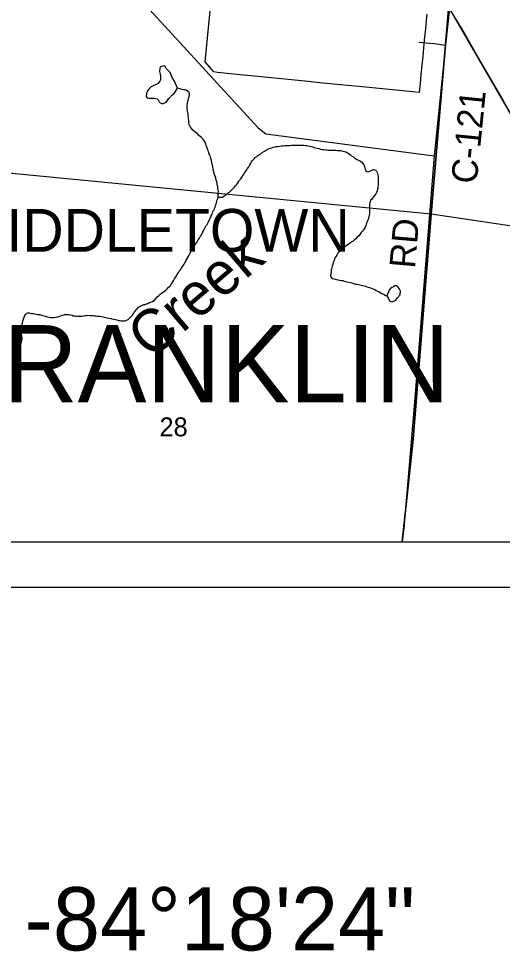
# Model space of a CAD drawing. Extents: x -7.3 to 34, y 0 to 22.
# Drawn here: x 6.481 to 7.551, y 13.194 to 15.258 of the extents above; entities that cross this region are included whole.
import ezdxf

# ---------------------------------------------------------------- set-up
doc = ezdxf.new("R2010")
doc.units = 0
for name, color, linetype in [('GM_X_Corporation', 7, 'Continuous'), ('GM_X_Corporation_Text', 7, 'Continuous'), ('GM_X_County_Road', 7, 'Continuous'), ('GM_X_County_Road_Text', 7, 'Continuous'), ('GM_X_Minor_River', 7, 'Continuous'), ('GM_X_Minor_River_Text', 7, 'Continuous'), ('GM_X_Rail_Line', 7, 'Continuous'), ('GM_X_Section_Text', 7, 'Continuous'), ('GM_X_State_Route', 7, 'Continuous'), ('GM_X_Township_Road', 7, 'Continuous'), ('GM_X_Township_Text', 7, 'Continuous'), ('SH_Data', 7, 'Continuous'), ('SH_Text', 7, 'Continuous')]:
    doc.layers.add(name, color=color, linetype=linetype)

msp = doc.modelspace()

# ---------------------------------------------------------------- linework, layer by layer
at = {"layer": 'GM_X_Corporation'}
for points in [[(4.3152, 15.5847), (4.2701, 15.1232), (4.2655, 15.0758), (4.2591, 15.0066), (4.246, 14.8644), (4.233, 14.7229), (4.2199, 14.5807), (4.1921, 14.279), (4.1756, 14.1), (8.9, 14.1), (8.9, 19.7858)], [(4.3152, 15.5847), (4.2701, 15.1232), (4.2655, 15.0758), (4.2591, 15.0066), (4.246, 14.8644), (4.233, 14.7229), (4.2199, 14.5807), (4.1921, 14.279), (4.1756, 14.1), (8.3447, 14.1), (8.3604, 14.2653), (8.3676, 14.3403), (8.3685, 14.3492), (8.4214, 14.9056), (8.4562, 15.2161), (8.4601, 15.2687)], [(7.3841, 15.2677), (7.3828, 15.254), (7.381, 15.2352), (7.3786, 15.2107), (7.3776, 15.2013), (7.375, 15.1745), (7.3731, 15.1544), (7.3711, 15.1342), (7.3691, 15.1141), (7.3671, 15.0939), (7.2494, 15.1056), (7.1858, 15.112), (7.1538, 15.1151), (7.1217, 15.1182), (6.9882, 15.1318), (6.9781, 15.1328), (6.9209, 15.1386), (6.9127, 15.1395), (6.8935, 15.1619), (6.8943, 15.1697), (6.9158, 15.3877)]]:
    msp.add_lwpolyline(points, dxfattribs=at)
for points in [[(6.4371, 15.9508), (7.4799, 15.8457), (7.3939, 14.8252), (6.3438, 14.9266)], [(7.4799, 15.8457), (8.4992, 15.7029), (8.4066, 14.6743), (7.3939, 14.8252)], [(6.2678, 14.1), (7.3299, 14.1), (7.354, 14.3269), (7.3939, 14.8252), (6.3438, 14.9266)], [(7.3299, 14.1), (8.355, 14.1), (8.4066, 14.6743), (7.3939, 14.8252), (7.354, 14.3269)]]:
    msp.add_lwpolyline(points, close=True, dxfattribs=at)
at = {"layer": 'GM_X_County_Road'}
for points in [[(5.9101, 15.654), (6.405, 15.6216), (6.39, 15.4485), (6.3969, 15.4388), (6.6396, 15.4146), (6.6541, 15.4047), (7.0106, 15.016), (7.0281, 15.003), (7.4002, 14.9537)], [(7.4344, 15.2802), (7.4256, 15.1989), (7.4002, 14.9537), (7.3569, 14.4092), (7.3329, 14.1292), (7.3296, 14.1)]]:
    msp.add_lwpolyline(points, dxfattribs=at)
at = {"layer": 'GM_X_Minor_River'}
for points in [[(6.8323, 15.1035), (6.8257, 15.1194), (6.8203, 15.1276), (6.8161, 15.1387), (6.8073, 15.1474), (6.8045, 15.1528), (6.7995, 15.1526), (6.7949, 15.1512), (6.7929, 15.1478), (6.7927, 15.1403), (6.7936, 15.1349), (6.7949, 15.1292), (6.7943, 15.122), (6.7931, 15.1193), (6.7891, 15.1138), (6.7837, 15.1113), (6.7783, 15.1088), (6.7741, 15.1067), (6.7697, 15.1022), (6.7662, 15.0978), (6.7633, 15.0918), (6.7631, 15.0854), (6.7653, 15.0823), (6.769, 15.0814), (6.7763, 15.0819), (6.7808, 15.0814), (6.7842, 15.0809), (6.7876, 15.0804), (6.7898, 15.078), (6.7916, 15.0738), (6.7941, 15.0714), (6.796, 15.0706), (6.7994, 15.0694)], [(6.7994, 15.0694), (6.8075, 15.0725), (6.8134, 15.0807), (6.8197, 15.0881), (6.8256, 15.0925), (6.8323, 15.1035)], [(6.9226, 14.8722), (6.9227, 14.8748), (6.9223, 14.8779), (6.9217, 14.8821), (6.9214, 14.8863), (6.9203, 14.8901), (6.92, 14.8931), (6.919, 14.8966), (6.9179, 14.9004), (6.9169, 14.905), (6.9154, 14.9088), (6.9144, 14.913), (6.913, 14.9176), (6.9123, 14.9218), (6.9112, 14.9252), (6.9102, 14.9298), (6.9095, 14.9333), (6.9092, 14.9359), (6.9085, 14.939), (6.9075, 14.9436), (6.906, 14.9478), (6.905, 14.9516), (6.9039, 14.9547), (6.9025, 14.9585), (6.9011, 14.9631), (6.9, 14.9658), (6.8989, 14.9684), (6.8971, 14.973), (6.896, 14.9769), (6.8953, 14.9795), (6.8932, 14.9841), (6.8906, 14.9884), (6.8888, 14.9911), (6.8854, 14.9942), (6.8824, 14.9965), (6.8798, 14.9992), (6.8772, 15.0016), (6.8732, 15.0055), (6.8698, 15.0078), (6.8664, 15.0106), (6.8639, 15.014), (6.8613, 15.0171), (6.8594, 15.0202), (6.8584, 15.0236), (6.8577, 15.0263), (6.8574, 15.0294), (6.8571, 15.0328), (6.8567, 15.0355), (6.8564, 15.0389), (6.8561, 15.0431), (6.8558, 15.0461), (6.8552, 15.0495), (6.8545, 15.0526), (6.8538, 15.0587), (6.8536, 15.0636), (6.8536, 15.0663), (6.8541, 15.0689), (6.8541, 15.0716), (6.8549, 15.0746), (6.8558, 15.0773), (6.8566, 15.0799), (6.8574, 15.0829), (6.8582, 15.0856), (6.8587, 15.089), (6.8591, 15.0916), (6.858, 15.0951), (6.8547, 15.0974), (6.8513, 15.099), (6.8487, 15.0998), (6.8453, 15.1003), (6.8419, 15.1011), (6.8385, 15.102), (6.8351, 15.1028), (6.8323, 15.1035)], [(6.9224, 14.8623), (6.9315, 14.8625), (6.9353, 14.8655), (6.938, 14.8669), (6.9419, 14.8702), (6.9454, 14.8725), (6.9481, 14.8747), (6.9515, 14.878), (6.955, 14.881), (6.9585, 14.8847), (6.9609, 14.8873), (6.9628, 14.8899), (6.9651, 14.8929), (6.9675, 14.8963), (6.9687, 14.8993), (6.9726, 14.9034), (6.9753, 14.9075), (6.9769, 14.9105), (6.98, 14.9139), (6.9816, 14.9169), (6.984, 14.9206), (6.9855, 14.9232), (6.9871, 14.9259), (6.9898, 14.93), (6.9922, 14.9341), (6.9946, 14.9379), (6.9962, 14.9409), (6.9985, 14.9439), (7.0016, 14.9472), (7.0043, 14.9506), (7.007, 14.952), (7.0101, 14.9546), (7.014, 14.9568), (7.0166, 14.9587), (7.0197, 14.9613), (7.0247, 14.9646), (7.0293, 14.9671), (7.0339, 14.9693), (7.0374, 14.9708), (7.0412, 14.9718), (7.045, 14.9729), (7.0481, 14.9736), (7.0507, 14.9743), (7.0546, 14.9749), (7.0587, 14.9756), (7.0622, 14.9759), (7.066, 14.9762), (7.0698, 14.9765), (7.0736, 14.9768), (7.077, 14.9771), (7.0808, 14.977), (7.0849, 14.9773), (7.0891, 14.9776), (7.0918, 14.9775), (7.0967, 14.9778), (7.1009, 14.9777), (7.1043, 14.9777), (7.1073, 14.9776), (7.1115, 14.9775), (7.1153, 14.977), (7.1183, 14.9766), (7.1213, 14.9761), (7.1243, 14.9753), (7.1281, 14.9745), (7.1315, 14.9736), (7.1349, 14.9724), (7.1379, 14.972), (7.1417, 14.9711), (7.1455, 14.9699), (7.1485, 14.9691), (7.1526, 14.9682), (7.156, 14.9678), (7.1598, 14.967), (7.1628, 14.9669), (7.1663, 14.9668), (7.1708, 14.9667), (7.1742, 14.9666), (7.1769, 14.9666), (7.1803, 14.9665), (7.1829, 14.9665), (7.1863, 14.966), (7.1901, 14.9659), (7.1928, 14.9655), (7.1954, 14.965), (7.1988, 14.9646), (7.2018, 14.9638), (7.2052, 14.9625), (7.2082, 14.9606), (7.2116, 14.959), (7.2142, 14.957), (7.2183, 14.9535), (7.2217, 14.9516), (7.2243, 14.9492), (7.2269, 14.9476), (7.2295, 14.9457), (7.2329, 14.9441), (7.2355, 14.9429), (7.2393, 14.9405), (7.2422, 14.9371), (7.2448, 14.934), (7.2463, 14.9305)], [(7.2463, 14.9305), (7.247, 14.9278), (7.2477, 14.9248), (7.2487, 14.9213), (7.2513, 14.919), (7.2547, 14.9189), (7.2578, 14.92), (7.2609, 14.9218), (7.2636, 14.9233), (7.267, 14.924), (7.2704, 14.9224), (7.273, 14.9197), (7.274, 14.917), (7.2751, 14.9139), (7.2758, 14.9112), (7.2761, 14.9086), (7.2761, 14.9059), (7.2764, 14.9025), (7.2763, 14.8998), (7.2766, 14.8964), (7.2766, 14.8938), (7.2765, 14.8907), (7.2761, 14.8881), (7.276, 14.8854), (7.2756, 14.8828), (7.2751, 14.8801), (7.2743, 14.8767), (7.2727, 14.8729), (7.2711, 14.8699), (7.2684, 14.8662), (7.266, 14.8632), (7.2641, 14.8606), (7.2621, 14.858), (7.2594, 14.8558), (7.2586, 14.8524), (7.2582, 14.8497), (7.2573, 14.8463), (7.2573, 14.8436), (7.2572, 14.8406), (7.2575, 14.8379), (7.2574, 14.8338), (7.2574, 14.8304), (7.2569, 14.8258), (7.2564, 14.8228), (7.2556, 14.8194), (7.2548, 14.816), (7.2543, 14.8133), (7.2531, 14.8103), (7.2515, 14.8062), (7.2499, 14.8028), (7.2491, 14.7998), (7.2475, 14.796), (7.2452, 14.7926), (7.2436, 14.79), (7.2416, 14.7874), (7.2389, 14.784), (7.2362, 14.7803), (7.233, 14.7766), (7.2303, 14.774), (7.2268, 14.7706), (7.2238, 14.7684), (7.221, 14.7654), (7.2168, 14.7632), (7.2141, 14.7606), (7.211, 14.7584), (7.2079, 14.7562), (7.2049, 14.754), (7.2022, 14.7521), (7.1991, 14.7496), (7.1964, 14.7477), (7.1937, 14.7455), (7.1906, 14.7421), (7.1875, 14.7384), (7.1855, 14.7358), (7.1835, 14.732), (7.1816, 14.729), (7.18, 14.726), (7.1788, 14.7226), (7.1776, 14.7196), (7.1771, 14.717), (7.1759, 14.7132), (7.1747, 14.7102), (7.1739, 14.7068), (7.1734, 14.7041), (7.1726, 14.7015), (7.1722, 14.6989), (7.1721, 14.6958), (7.1717, 14.6924), (7.1712, 14.6898), (7.1712, 14.6867), (7.173, 14.684), (7.1756, 14.6824), (7.1786, 14.682), (7.1817, 14.6812), (7.1843, 14.6804), (7.1877, 14.6795), (7.1907, 14.6791), (7.1945, 14.6782), (7.1979, 14.6778), (7.2009, 14.677), (7.2035, 14.6761)], [(6.6908, 14.5927), (6.695, 14.5918), (6.698, 14.591), (6.7014, 14.5898), (6.7052, 14.5893), (6.7086, 14.5889), (6.7127, 14.5888), (6.7162, 14.5891), (6.7196, 14.5901), (6.723, 14.592), (6.7261, 14.5946), (6.7296, 14.5983), (6.7327, 14.6016), (6.7351, 14.6054), (6.7367, 14.608), (6.7386, 14.6106), (6.7406, 14.6132), (6.7433, 14.6155), (6.7456, 14.6188), (6.7487, 14.6203), (6.7514, 14.6221), (6.7545, 14.6236), (6.7575, 14.6247), (6.7609, 14.6253), (6.7636, 14.6264), (6.7667, 14.6275), (6.7705, 14.6297), (6.7755, 14.6307), (6.7786, 14.6326), (6.7813, 14.6348), (6.7844, 14.6381), (6.7867, 14.6411), (6.7906, 14.6452), (6.7941, 14.6482), (6.7979, 14.6511), (6.801, 14.653), (6.8041, 14.6552), (6.8076, 14.6581), (6.8103, 14.6607), (6.8122, 14.6634), (6.8157, 14.6659), (6.8173, 14.6686), (6.8196, 14.6716), (6.8216, 14.6753), (6.8239, 14.6791), (6.8259, 14.6821), (6.8286, 14.6862), (6.8314, 14.6911), (6.833, 14.6937), (6.8361, 14.6986), (6.8381, 14.7012), (6.8412, 14.706), (6.844, 14.7098), (6.8467, 14.7143), (6.8483, 14.7169), (6.8499, 14.7195), (6.8518, 14.7233), (6.8538, 14.727), (6.8562, 14.7308), (6.8581, 14.7345), (6.8601, 14.7383), (6.8621, 14.7424), (6.8652, 14.7469), (6.8668, 14.7499), (6.868, 14.7526), (6.87, 14.7559), (6.8727, 14.7593), (6.8747, 14.7623), (6.8766, 14.7653), (6.8782, 14.7683), (6.8806, 14.772), (6.8833, 14.7762), (6.8853, 14.7795), (6.8869, 14.7825), (6.8885, 14.7856), (6.8905, 14.7897), (6.8928, 14.7938), (6.8944, 14.7968), (6.896, 14.7998), (6.8976, 14.8024), (6.8999, 14.8062), (6.9019, 14.8103), (6.9035, 14.8133), (6.9047, 14.8164), (6.9063, 14.8197), (6.9079, 14.8235), (6.9091, 14.8265), (6.9103, 14.8295), (6.9115, 14.8322), (6.9131, 14.8348), (6.9142, 14.8374), (6.9154, 14.8401), (6.9167, 14.8438), (6.9175, 14.8472), (6.9187, 14.851), (6.9203, 14.8563), (6.9216, 14.8593), (6.9224, 14.8623), (6.9224, 14.865), (6.9225, 14.8684), (6.9226, 14.8722)], [(7.2035, 14.6761), (7.2077, 14.6753), (7.2111, 14.6745), (7.2141, 14.674), (7.2183, 14.6728), (7.2209, 14.672), (7.2243, 14.6711), (7.2273, 14.6703), (7.23, 14.6699), (7.233, 14.6694), (7.236, 14.6686), (7.239, 14.6678), (7.2424, 14.6669), (7.2454, 14.6661), (7.2481, 14.6653), (7.2511, 14.6645), (7.2545, 14.6636), (7.2571, 14.6628), (7.2597, 14.6616), (7.2628, 14.6604), (7.2654, 14.6596), (7.2688, 14.658), (7.2718, 14.6564), (7.2751, 14.6548), (7.2778, 14.6536), (7.2811, 14.6517), (7.2838, 14.6497), (7.2868, 14.6485), (7.2898, 14.6473), (7.2928, 14.645), (7.2954, 14.6441)], [(7.3227, 14.6604), (7.3208, 14.6631), (7.3175, 14.6662), (7.3134, 14.6664), (7.3102, 14.6638), (7.3064, 14.6624), (7.3029, 14.6599), (7.3005, 14.6569), (7.2954, 14.6441)], [(7.2954, 14.6441), (7.2995, 14.6387), (7.3016, 14.6333), (7.3076, 14.6312), (7.3153, 14.6348), (7.3189, 14.6396), (7.3252, 14.6462), (7.3255, 14.6542), (7.3227, 14.6604)], [(6.4799, 14.5228), (6.4811, 14.5262), (6.4816, 14.5288), (6.4832, 14.5322), (6.4848, 14.5356), (6.486, 14.5386), (6.4868, 14.5416), (6.488, 14.545), (6.4884, 14.5477), (6.4881, 14.5511), (6.4878, 14.5538), (6.4879, 14.5564), (6.4872, 14.5591), (6.4869, 14.5625), (6.4869, 14.5656), (6.487, 14.5686), (6.4871, 14.5716), (6.4875, 14.5754), (6.488, 14.5781), (6.4884, 14.5811), (6.4892, 14.5845), (6.4897, 14.5875), (6.4909, 14.5909), (6.4921, 14.5947), (6.4929, 14.5974), (6.4945, 14.6004), (6.4961, 14.603), (6.4984, 14.6056), (6.5011, 14.6063), (6.5038, 14.6066), (6.5064, 14.6058), (6.5094, 14.605), (6.5128, 14.6053), (6.5162, 14.6044), (6.5196, 14.6036), (6.523, 14.6032), (6.5272, 14.6027), (6.531, 14.6015), (6.534, 14.601), (6.5374, 14.6002), (6.5404, 14.5994), (6.5445, 14.5981), (6.5479, 14.5969), (6.5509, 14.5965), (6.554, 14.596), (6.5582, 14.5963), (6.5631, 14.597), (6.5673, 14.598), (6.5719, 14.5994), (6.5757, 14.6009), (6.5787, 14.6016), (6.5822, 14.6026), (6.5852, 14.6033), (6.5886, 14.6032), (6.5924, 14.6028), (6.5954, 14.602), (6.5988, 14.6011), (6.6015, 14.6003), (6.606, 14.5998), (6.6094, 14.5994), (6.6124, 14.5989), (6.6162, 14.5989), (6.6204, 14.5995), (6.6246, 14.6002), (6.628, 14.6009), (6.6311, 14.6008), (6.6341, 14.6011), (6.6383, 14.601), (6.6421, 14.6009), (6.6459, 14.6005), (6.6489, 14.6), (6.6515, 14.6), (6.6542, 14.5995), (6.6572, 14.5991), (6.661, 14.599), (6.6648, 14.5982), (6.6674, 14.5977), (6.6704, 14.5969), (6.6738, 14.5965), (6.6769, 14.5956), (6.6806, 14.5948), (6.6844, 14.594), (6.6871, 14.5935), (6.6908, 14.5927)]]:
    msp.add_lwpolyline(points, dxfattribs=at)
at = {"layer": 'GM_X_Rail_Line'}
msp.add_lwpolyline([(8.1171, 14.1), (7.77, 14.7008), (7.4272, 15.293), (6.5394, 16.8246), (6.3886, 17.0851), (6.2996, 17.2555), (6.2775, 17.3138), (6.2567, 17.3864), (6.213, 17.5514), (6.1948, 17.6035), (6.1703, 17.6358), (6.1218, 17.6697), (5.9568, 17.7678)], dxfattribs=at)
at = {"layer": 'GM_X_State_Route'}
msp.add_lwpolyline([(8.0558, 14.2031), (8.0084, 14.2839), (7.9897, 14.3165), (7.9577, 14.3718), (7.9127, 14.4514), (7.8775, 14.5131), (7.8704, 14.526), (7.7981, 14.651), (7.748, 14.7378), (7.707, 14.8101), (7.664, 14.8848), (7.6231, 14.9559), (7.5815, 15.0273), (7.5477, 15.0857), (7.4974, 15.1731), (7.4652, 15.2288), (7.4344, 15.2802)], dxfattribs=at)
at = {"layer": 'GM_X_Township_Road'}
msp.add_line((7.3667, 15.2058), (7.3905, 15.2034), dxfattribs=at)
msp.add_lwpolyline([(7.3905, 15.2034), (7.4001, 15.2024), (7.4256, 15.1989)], dxfattribs=at)
at = {"layer": 'SH_Data'}
for p, q in [((2.1, 14.1), (8.9, 14.1)), ((2, 14), (9, 14))]:
    msp.add_line(p, q, dxfattribs=at)

# ---------------------------------------------------------------- texts
at = {"layer": 'GM_X_Corporation_Text'}
msp.add_text('MIDDLETOWN', height=0.0947, rotation=0, dxfattribs=at).set_placement((6.3481, 14.7417))
at = {"layer": 'GM_X_County_Road_Text'}
for s, rotation, p in [('C-121', 84.3106, (7.4943, 14.8906)), ('RD', 85.0738, (7.3578, 14.7036))]:
    msp.add_text(s, height=0.05682, rotation=rotation, dxfattribs=at).set_placement(p)
at = {"layer": 'GM_X_Minor_River_Text'}
msp.add_text('Creek', height=0.09469, rotation=40.4228, dxfattribs=at).set_placement((6.7732, 14.5012))
at = {"layer": 'GM_X_Section_Text'}
msp.add_text('28', height=0.04186, rotation=0, dxfattribs=at).set_placement((6.7925, 14.3334))
at = {"layer": 'GM_X_Township_Text'}
msp.add_text('FRANKLIN', height=0.17045, rotation=0, dxfattribs=at).set_placement((6.3076, 14.4089))
at = {"layer": 'SH_Text'}
msp.add_text('LATITUDE:  39 °33\'29"     LONGITUDE:  -84°18\'24"', height=0.14, dxfattribs=at).set_placement((3.071, 13.1959))

doc.saveas('drawing.dxf')
